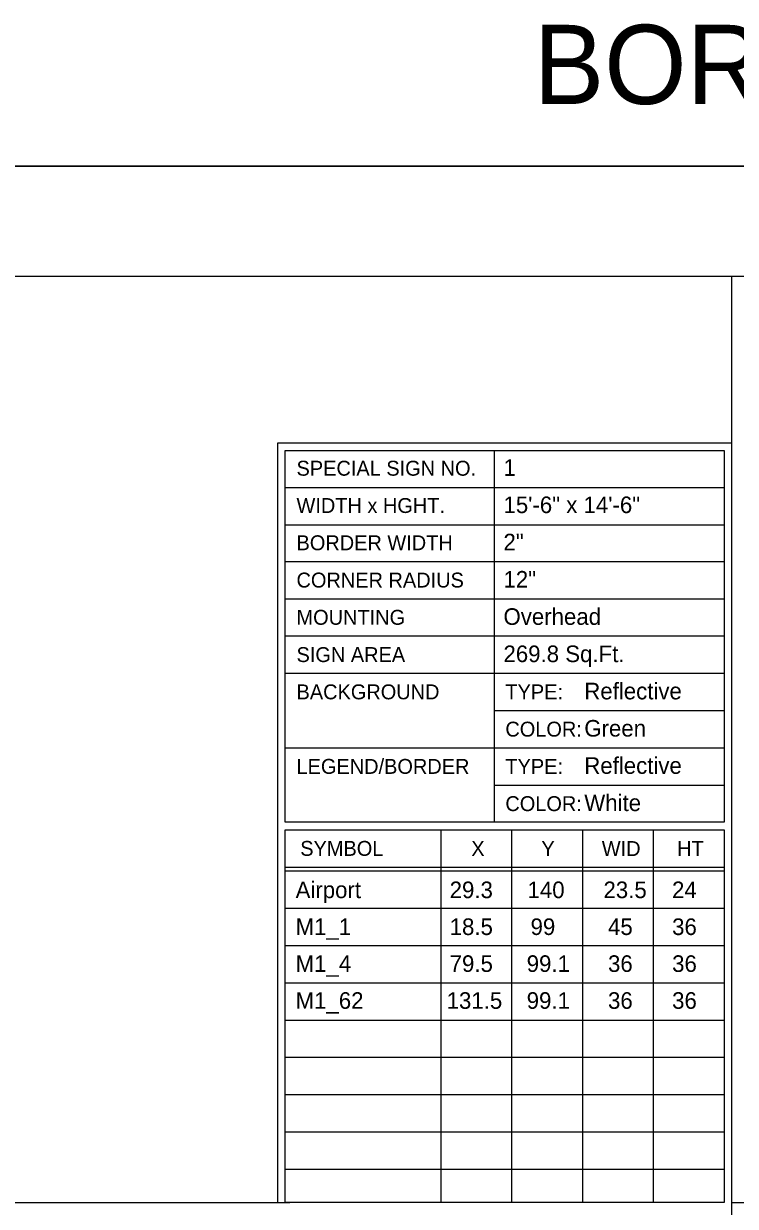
# Model space of a CAD drawing. Extents: x 2149961 to 2150220, y 145114 to 145240.
# Drawn here: x 2150054.31 to 2150076.43, y 145187.59 to 145224.38 of the extents above; entities that cross this region are included whole.
import ezdxf

# ---------------------------------------------------------------- set-up
doc = ezdxf.new("R2010")
doc.units = 0
for name, color, linetype in [('BORDER', 7, 'Continuous'), ('GSSHT', 7, 'Continuous'), ('Level 1', 7, 'Continuous'), ('PDF', 7, 'Continuous'), ('TEXT', 7, 'Continuous')]:
    doc.layers.add(name, color=color, linetype=linetype)

msp = doc.modelspace()

# ---------------------------------------------------------------- linework, layer by layer
at = {"layer": 'BORDER'}
for p, q in [((2150010.458, 145219.948), (2150174.061, 145219.948)), ((2150171.536, 145216.512), (2150017.557, 145216.512))]:
    msp.add_line(p, q, dxfattribs=at)
at = {"layer": 'Level 1'}
for p, q in [((2150076.316, 145216.512), (2150076.316, 145117.388)), ((2150062.21, 145211.34), (2150076.316, 145211.34)), ((2150068.935, 145211.108), (2150068.935, 145199.537)), ((2150062.442, 145209.949), (2150076.084, 145209.949)), ((2150062.442, 145208.789), (2150076.084, 145208.789)), ((2150062.442, 145207.653), (2150076.084, 145207.653)), ((2150062.442, 145206.494), (2150076.084, 145206.494)), ((2150062.442, 145205.334), (2150076.084, 145205.334)), ((2150062.442, 145204.175), (2150076.084, 145204.175)), ((2150068.935, 145203.015), (2150076.084, 145203.015)), ((2150062.442, 145201.856), (2150076.084, 145201.856)), ((2150068.935, 145200.696), (2150076.084, 145200.696)), ((2150062.442, 145187.705), (2150062.442, 145199.305)), ((2150062.442, 145199.305), (2150076.084, 145199.305)), ((2150067.272, 145199.299), (2150067.272, 145198.14)), ((2150069.475, 145199.299), (2150069.475, 145198.14)), ((2150071.678, 145199.299), (2150071.678, 145198.14)), ((2150073.881, 145199.299), (2150073.881, 145198.14)), ((2150076.084, 145199.305), (2150076.084, 145187.705)), ((2150062.442, 145198.14), (2150076.084, 145198.14)), ((2150067.272, 145198.14), (2150067.272, 145187.705)), ((2150069.475, 145198.14), (2150069.475, 145187.705)), ((2150071.678, 145198.14), (2150071.678, 145187.705)), ((2150073.881, 145198.14), (2150073.881, 145187.705)), ((2150062.442, 145198.024), (2150076.084, 145198.024)), ((2150062.442, 145196.864), (2150076.084, 145196.864)), ((2150062.442, 145195.705), (2150076.084, 145195.705)), ((2150062.442, 145194.545), (2150076.084, 145194.545)), ((2150062.442, 145193.386), (2150076.084, 145193.386)), ((2150062.442, 145192.227), (2150076.084, 145192.227)), ((2150062.442, 145191.067), (2150076.084, 145191.067)), ((2150062.442, 145189.908), (2150076.084, 145189.908)), ((2150062.442, 145188.748), (2150076.084, 145188.748)), ((2150017.557, 145187.705), (2150062.583, 145187.705)), ((2150076.084, 145187.705), (2150062.442, 145187.705)), ((2150076.316, 145187.705), (2150121.342, 145187.705))]:
    msp.add_line(p, q, dxfattribs=at)
msp.add_lwpolyline([(2150062.21, 145187.705), (2150062.21, 145211.34)], dxfattribs=at)
msp.add_lwpolyline([(2150062.442, 145211.108), (2150076.084, 145211.108), (2150076.084, 145199.537), (2150062.442, 145199.537)], close=True, dxfattribs=at)
at = {"layer": 'PDF'}
msp.add_lwpolyline([(2150010.458, 145114.088), (2150174.061, 145114.088), (2150174.061, 145219.948), (2150010.458, 145219.948)], close=True, dxfattribs=at)

# ---------------------------------------------------------------- texts
at = {"layer": 'GSSHT'}
for s, height, p in [('1', 0.517, (2150069.224, 145210.315)), ('Overhead', 0.5165, (2150069.224, 145205.679))]:
    msp.add_text(s, height=height, dxfattribs=at).set_placement(p)
at = {"layer": 'Level 1'}
for s, height, p in [('SPECIAL SIGN NO.', 0.46374, (2150062.79, 145210.32)), ('WIDTH x HGHT.', 0.46374, (2150062.79, 145209.16)), ('15\'-6" x 14\'-6"', 0.51652, (2150069.224, 145209.156)), ('BORDER WIDTH', 0.46374, (2150062.79, 145208.001)), ('2"', 0.5165, (2150069.224, 145207.997)), ('CORNER RADIUS', 0.46374, (2150062.79, 145206.841)), ('12"', 0.5165, (2150069.224, 145206.838)), ('MOUNTING', 0.4637, (2150062.79, 145205.682)), ('SIGN AREA', 0.4638, (2150062.79, 145204.522)), ('269.8 Sq.Ft.', 0.51652, (2150069.224, 145204.52)), ('BACKGROUND', 0.4637, (2150062.79, 145203.363)), ('TYPE:', 0.4637, (2150069.283, 145203.363)), ('Reflective', 0.5165, (2150071.736, 145203.361)), ('COLOR:', 0.4637, (2150069.283, 145202.203)), ('Green', 0.5165, (2150071.736, 145202.203)), ('LEGEND/BORDER', 0.46374, (2150062.79, 145201.044)), ('TYPE:', 0.4637, (2150069.283, 145201.044)), ('Reflective', 0.5165, (2150071.736, 145201.044)), ('COLOR:', 0.4637, (2150069.283, 145199.885)), ('White', 0.5165, (2150071.736, 145199.885)), ('SYMBOL', 0.4637, (2150062.906, 145198.493)), ('X', 0.464, (2150068.223, 145198.488)), ('Y', 0.464, (2150070.403, 145198.488)), ('WID', 0.4637, (2150072.281, 145198.488)), ('HT', 0.4637, (2150074.623, 145198.488)), ('Airport', 0.5165, (2150062.761, 145197.177)), ('29.3', 0.5165, (2150067.551, 145197.177)), ('140', 0.5165, (2150069.972, 145197.177)), ('23.5', 0.5165, (2150072.333, 145197.177)), ('24', 0.5165, (2150074.464, 145197.177)), ('M1_1', 0.5165, (2150062.761, 145196.03)), ('18.5', 0.5165, (2150067.551, 145196.03)), ('99', 0.5165, (2150070.066, 145196.03)), ('45', 0.5165, (2150072.474, 145196.03)), ('36', 0.5165, (2150074.467, 145196.03)), ('M1_4', 0.5165, (2150062.761, 145194.882)), ('79.5', 0.5165, (2150067.551, 145194.882)), ('99.1', 0.5165, (2150069.946, 145194.882)), ('36', 0.5165, (2150072.474, 145194.882)), ('36', 0.5165, (2150074.467, 145194.882)), ('M1_62', 0.5165, (2150062.761, 145193.734)), ('131.5', 0.5165, (2150067.457, 145193.734)), ('99.1', 0.5165, (2150069.946, 145193.734)), ('36', 0.5165, (2150072.474, 145193.734)), ('36', 0.5165, (2150074.467, 145193.734))]:
    msp.add_text(s, height=height, dxfattribs=at).set_placement(p)
at = {"layer": 'TEXT'}
msp.add_text('BORDER AND REPORT 70 SCALE', height=2.46401, dxfattribs=at).set_placement((2150070.157, 145221.883))

doc.saveas('drawing.dxf')
